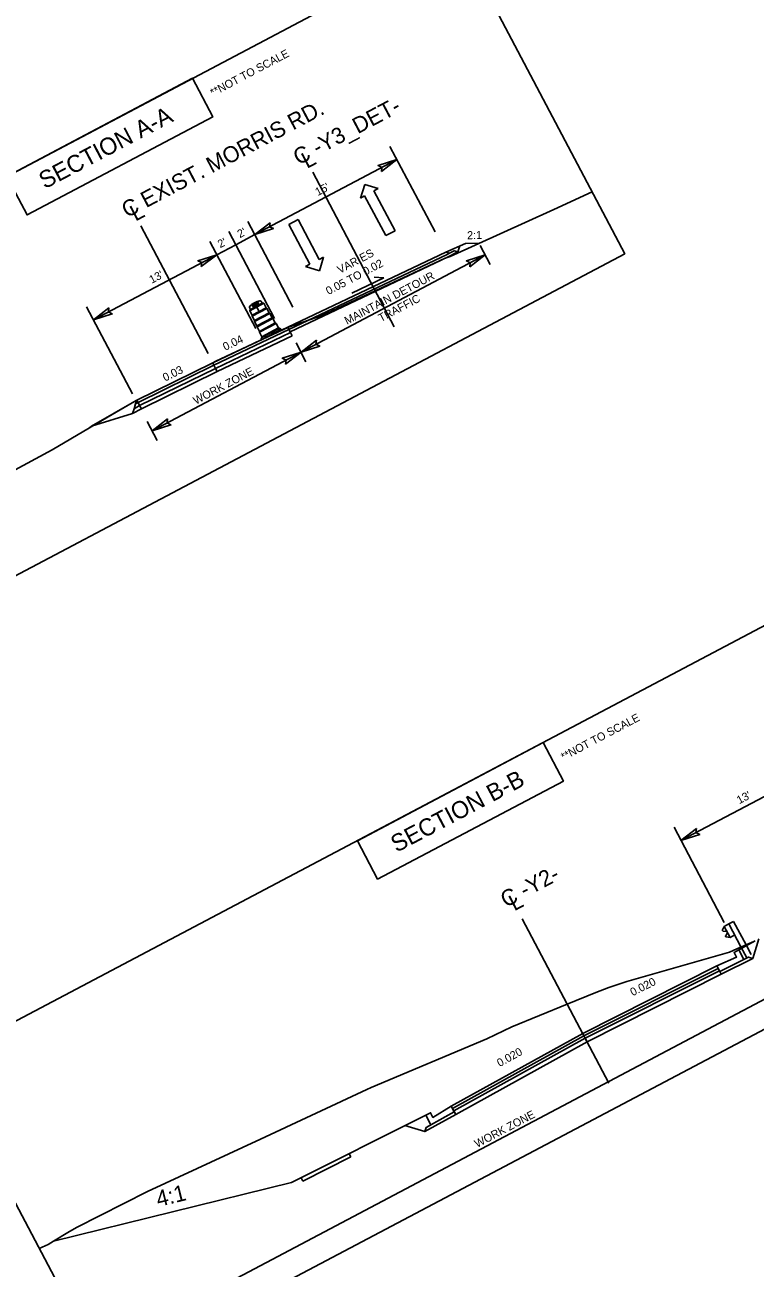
# Model space of a CAD drawing. Extents: x 1487176 to 1495274, y 497106 to 503692.
# Drawn here: x 1488684.4 to 1488752.5, y 497172.6 to 497288.5 of the extents above; entities that cross this region are included whole.
import ezdxf

# ---------------------------------------------------------------- set-up
doc = ezdxf.new("R2010")
doc.units = 0
for name, color, linetype in [('Default', 7, 'Continuous'), ('Exist XS Ground Line', 7, 'Continuous'), ('Prop Terminator CELL', 7, 'Continuous'), ('Typical Guardrail CELL', 7, 'Continuous'), ('Typical Hinge Slope Interstate CELL', 7, 'Continuous'), ('Typical Pavement Slope Information CELL', 7, 'Continuous'), ('WZ OSDR CELL', 7, 'Continuous')]:
    doc.layers.add(name, color=color, linetype=linetype)

msp = doc.modelspace()

# ---------------------------------------------------------------- linework, layer by layer
at = {"layer": 'Default'}
for p, q in [((1488722.67, 497269.16), (1488718.45, 497277.14)), ((1488719.1, 497275.91), (1488705.84, 497268.91)), ((1488718.85, 497260.33), (1488711.25, 497274.72)), ((1488716.1, 497273.6), (1488715.69, 497272.32)), ((1488717.36, 497273.2), (1488716.1, 497273.6)), ((1488716.96, 497272.99), (1488717.36, 497273.2)), ((1488718.92, 497269.28), (1488716.96, 497272.99)), ((1488715.69, 497272.32), (1488716.09, 497272.53)), ((1488716.09, 497272.53), (1488718.05, 497268.82)), ((1488701.51, 497257.82), (1488695.23, 497269.73)), ((1488709.4, 497262.16), (1488705.19, 497270.13)), ((1488709.01, 497269.86), (1488709.89, 497270.33)), ((1488710.97, 497266.15), (1488709.01, 497269.86)), ((1488709.89, 497270.33), (1488711.85, 497266.61)), ((1488718.05, 497268.82), (1488718.92, 497269.28)), ((1488705.93, 497260.16), (1488701.65, 497268.26)), ((1488707.7, 497261.09), (1488703.42, 497269.2)), ((1488704.07, 497267.97), (1488705.84, 497268.91)), ((1488702.3, 497267.04), (1488690.8, 497260.97)), ((1488702.3, 497267.04), (1488704.07, 497267.97)), ((1488727.33, 497267.02), (1488710.16, 497257.95)), ((1488727.8, 497266.14), (1488726.87, 497267.91)), ((1488710.58, 497265.94), (1488710.97, 497266.15)), ((1488711.87, 497265.55), (1488710.58, 497265.94)), ((1488711.85, 497266.61), (1488712.25, 497266.82)), ((1488712.25, 497266.82), (1488711.87, 497265.55)), ((1488694.44, 497254.09), (1488690.16, 497262.19)), ((1488709.15, 497259.86), (1488708.92, 497260.3)), ((1488710.62, 497257.07), (1488709.69, 497258.84)), ((1488710.16, 497257.95), (1488696.27, 497250.62)), ((1488696.74, 497249.74), (1488695.8, 497251.5)), ((1488757.08, 497218.52), (1488745.58, 497212.45)), ((1488749.62, 497204.81), (1488744.94, 497213.68)), ((1488766.66, 497204.67), (1488692.23, 497165.37)), ((1488730.77, 497205.16), (1488738.86, 497189.84)), ((1488714.79, 497182.96), (1488714.64, 497183.25)), ((1488710.32, 497180.71), (1488710.17, 497181.01))]:
    msp.add_line(p, q, dxfattribs=at)
for points in [[(1488657.96, 497261.26), (1488724.81, 497296.56), (1488740.34, 497267.13), (1488673.49, 497231.84)], [(1488682.73, 497274.34), (1488700.04, 497283.48), (1488701.93, 497279.89), (1488684.62, 497270.75)], [(1488676.52, 497191.9), (1488777.22, 497245.07), (1488792.75, 497215.65), (1488692.05, 497162.48)], [(1488715.41, 497212.43), (1488732.73, 497221.58), (1488734.62, 497217.99), (1488717.3, 497208.85)], [(1488736.54, 497194.24), (1488736.48, 497194.35), (1488736.48, 497194.35), (1488736.54, 497194.24)], [(1488736.54, 497194.24), (1488736.48, 497194.35), (1488736.48, 497194.35), (1488736.54, 497194.24)]]:
    msp.add_lwpolyline(points, close=True, dxfattribs=at)
for points in [[(1488723.65, 497267.29), (1488725.5, 497268.09)], [(1488725.5, 497268.09), (1488726.76, 497268.11)], [(1488708.92, 497260.3), (1488723.65, 497267.29)], [(1488708.92, 497260.3), (1488723.65, 497267.29)], [(1488708.92, 497260.3), (1488723.65, 497267.29)], [(1488723.77, 497267.07), (1488709.03, 497260.08)], [(1488709.03, 497260.08), (1488723.77, 497267.07)], [(1488723.65, 497267.29), (1488723.65, 497267.29)], [(1488723.65, 497267.29), (1488723.65, 497267.29)], [(1488723.65, 497267.29), (1488724, 497267.19)], [(1488723.77, 497267.07), (1488724, 497267.19), (1488724.44, 497267.41), (1488724.79, 497267.31)], [(1488724, 497267.19), (1488723.77, 497267.07)], [(1488724.79, 497267.31), (1488723.89, 497266.85)], [(1488723.89, 497266.85), (1488724.79, 497267.31)], [(1488724.79, 497267.31), (1488724.96, 497267.86)], [(1488709.15, 497259.86), (1488723.89, 497266.85)], [(1488723.89, 497266.85), (1488709.15, 497259.86)], [(1488701.92, 497256.97), (1488708.92, 497260.3)], [(1488701.92, 497256.97), (1488708.92, 497260.3)], [(1488709.03, 497260.08), (1488702.04, 497256.75)], [(1488702.04, 497256.75), (1488709.03, 497260.08)], [(1488708.92, 497260.3), (1488708.92, 497260.3)], [(1488709.03, 497260.08), (1488708.92, 497260.3)], [(1488708.92, 497260.3), (1488708.92, 497260.3)], [(1488708.92, 497260.3), (1488709.03, 497260.08)], [(1488709.19, 497259.79), (1488709.03, 497260.08)], [(1488709.03, 497260.08), (1488709.19, 497259.79)], [(1488709.19, 497259.79), (1488702.19, 497256.45)], [(1488702.19, 497256.45), (1488709.19, 497259.79)], [(1488702.35, 497256.16), (1488709.34, 497259.49)], [(1488709.34, 497259.49), (1488702.35, 497256.16)], [(1488709.34, 497259.49), (1488709.19, 497259.79)], [(1488709.19, 497259.79), (1488709.34, 497259.49)], [(1488701.92, 497256.97), (1488694.84, 497253.49)], [(1488701.92, 497256.97), (1488694.84, 497253.49)], [(1488694.96, 497253.27), (1488702.04, 497256.75)], [(1488702.04, 497256.75), (1488694.96, 497253.27)], [(1488702.04, 497256.75), (1488701.92, 497256.97)], [(1488702.04, 497256.75), (1488701.92, 497256.97)], [(1488702.19, 497256.45), (1488702.04, 497256.75)], [(1488702.19, 497256.45), (1488702.04, 497256.75)], [(1488695.11, 497252.98), (1488702.19, 497256.45)], [(1488702.19, 497256.45), (1488695.11, 497252.98)], [(1488702.35, 497256.16), (1488695.27, 497252.68)], [(1488695.27, 497252.68), (1488702.35, 497256.16)], [(1488702.35, 497256.16), (1488702.19, 497256.45)], [(1488702.35, 497256.16), (1488702.19, 497256.45)], [(1488694.84, 497253.49), (1488690.61, 497251.05)], [(1488694.96, 497253.27), (1488694.73, 497253.15), (1488694.59, 497252.69)], [(1488694.84, 497253.49), (1488694.73, 497253.15)], [(1488694.73, 497253.15), (1488694.96, 497253.27)], [(1488694.84, 497253.49), (1488694.84, 497253.49)], [(1488694.96, 497253.27), (1488694.84, 497253.49)], [(1488694.84, 497253.49), (1488694.84, 497253.49)], [(1488694.84, 497253.49), (1488694.96, 497253.27)], [(1488695.11, 497252.98), (1488694.96, 497253.27)], [(1488694.96, 497253.27), (1488695.11, 497252.98)], [(1488694.45, 497252.23), (1488690.61, 497251.05)], [(1488694.59, 497252.69), (1488694.45, 497252.23)], [(1488694.45, 497252.23), (1488695.27, 497252.68)], [(1488695.27, 497252.68), (1488694.45, 497252.23)], [(1488694.59, 497252.69), (1488695.11, 497252.98)], [(1488695.11, 497252.98), (1488694.59, 497252.69)], [(1488694.59, 497252.69), (1488694.59, 497252.69)], [(1488695.27, 497252.68), (1488695.11, 497252.98)], [(1488695.11, 497252.98), (1488695.27, 497252.68)], [(1488690.61, 497251.05), (1488690.45, 497250.91), (1488690.4, 497250.96)], [(1488749.34, 497199.98), (1488752.29, 497201.46), (1488752.85, 497203.27)], [(1488748.93, 497200.75), (1488750.76, 497201.58), (1488750.53, 497202.02), (1488750.97, 497202.26)], [(1488750.97, 497202.26), (1488751.44, 497201.36), (1488749.21, 497200.24)], [(1488750.76, 497201.58), (1488750.53, 497202.02), (1488750.97, 497202.26)], [(1488750.97, 497202.26), (1488752.5, 497203.1)], [(1488748.93, 497200.75), (1488750.76, 497201.58)], [(1488749.21, 497200.24), (1488751.89, 497201.58), (1488752.29, 497201.46)], [(1488752.29, 497201.46), (1488749.34, 497199.98)], [(1488736.42, 497194.46), (1488748.93, 497200.75)], [(1488736.42, 497194.46), (1488748.93, 497200.75)], [(1488736.54, 497194.24), (1488749.05, 497200.53)], [(1488749.05, 497200.53), (1488736.54, 497194.24)], [(1488749.17, 497200.31), (1488736.66, 497194.02)], [(1488736.66, 497194.02), (1488749.17, 497200.31)], [(1488749.34, 497199.98), (1488736.83, 497193.69)], [(1488736.83, 497193.69), (1488749.34, 497199.98)], [(1488749.21, 497200.24), (1488748.93, 497200.75)], [(1488748.93, 497200.75), (1488749.05, 497200.53)], [(1488749.05, 497200.53), (1488749.17, 497200.31)], [(1488749.17, 497200.31), (1488749.34, 497199.98)], [(1488749.34, 497199.98), (1488749.21, 497200.24)], [(1488736.42, 497194.46), (1488724.17, 497187.68)], [(1488736.42, 497194.46), (1488724.17, 497187.68)], [(1488736.54, 497194.24), (1488724.29, 497187.46)], [(1488724.29, 497187.46), (1488736.54, 497194.24)], [(1488724.41, 497187.24), (1488736.66, 497194.02)], [(1488736.66, 497194.02), (1488724.41, 497187.24)], [(1488736.54, 497194.24), (1488736.42, 497194.46)], [(1488736.54, 497194.24), (1488736.42, 497194.46)], [(1488736.66, 497194.02), (1488736.54, 497194.24)], [(1488736.66, 497194.02), (1488736.54, 497194.24)], [(1488736.83, 497193.69), (1488736.66, 497194.02)], [(1488736.83, 497193.69), (1488736.66, 497194.02)], [(1488724.58, 497186.9), (1488736.83, 497193.69)], [(1488736.83, 497193.69), (1488724.58, 497186.9)], [(1488724.45, 497187.16), (1488721.82, 497185.71), (1488721.7, 497185.31)], [(1488724.17, 497187.68), (1488722.46, 497186.64), (1488722.23, 497187.08), (1488721.78, 497186.85)], [(1488721.78, 497186.85), (1488722.26, 497185.95), (1488724.45, 497187.16)], [(1488722.46, 497186.64), (1488722.23, 497187.08), (1488721.78, 497186.85)], [(1488724.17, 497187.68), (1488722.46, 497186.64)], [(1488724.45, 497187.16), (1488724.17, 497187.68)], [(1488724.17, 497187.68), (1488724.29, 497187.46)], [(1488724.29, 497187.46), (1488724.41, 497187.24)], [(1488724.41, 497187.24), (1488724.58, 497186.9)], [(1488724.58, 497186.9), (1488724.45, 497187.16)], [(1488721.78, 497186.85), (1488709.27, 497180.56), (1488687.09, 497175.11)], [(1488724.58, 497186.9), (1488721.7, 497185.31), (1488719.85, 497185.87)], [(1488721.7, 497185.31), (1488724.58, 497186.9)], [(1488714.79, 497182.96), (1488710.32, 497180.71)]]:
    msp.add_lwpolyline(points, dxfattribs=at)
at = {"layer": 'Exist XS Ground Line'}
for points in [[(1488669.29, 497239.8), (1488674.04, 497241.95), (1488674.67, 497242.24), (1488675.03, 497242.43), (1488686.96, 497248.87), (1488692.19, 497251.92), (1488694.78, 497253.44), (1488701.92, 497256.97), (1488702.21, 497257.11), (1488708.98, 497260.28), (1488712.18, 497261.42), (1488720.16, 497265.1), (1488723.61, 497266.71), (1488724.06, 497266.89), (1488733.72, 497271.27), (1488737.3, 497272.89)], [(1488687.09, 497175.11), (1488688.41, 497175.9), (1488689.23, 497176.38), (1488695.85, 497179.73), (1488706.39, 497184.61), (1488716.29, 497189.25), (1488716.69, 497189.42), (1488727.49, 497193.97), (1488729.81, 497195.08), (1488734.98, 497197.2), (1488737.63, 497198.28), (1488738.86, 497198.75), (1488740.52, 497199.31), (1488750.1, 497202.05), (1488750.79, 497202.35), (1488752.36, 497203.04), (1488752.5, 497203.1)], [(1488685.75, 497174.42), (1488686.57, 497174.8), (1488687.09, 497175.11)]]:
    msp.add_lwpolyline(points, dxfattribs=at)
at = {"layer": 'Prop Terminator CELL'}
for points in [[(1488717.65, 497274.8), (1488719.1, 497275.91), (1488717.35, 497275.35), (1488717.7, 497275.17)], [(1488707.28, 497270.02), (1488705.84, 497268.91), (1488707.59, 497269.47), (1488707.23, 497269.65)], [(1488700.85, 497265.93), (1488702.3, 497267.04), (1488700.55, 497266.48), (1488700.9, 497266.3)], [(1488725.89, 497265.91), (1488727.33, 497267.02), (1488725.58, 497266.46), (1488725.94, 497266.28)], [(1488692.25, 497262.08), (1488690.8, 497260.97), (1488692.55, 497261.53), (1488692.2, 497261.71)], [(1488711.6, 497259.07), (1488710.16, 497257.95), (1488711.91, 497258.52), (1488711.55, 497258.69)], [(1488708.71, 497256.84), (1488710.16, 497257.95), (1488708.41, 497257.39), (1488708.76, 497257.22)], [(1488697.72, 497251.73), (1488696.27, 497250.62), (1488698.02, 497251.18), (1488697.67, 497251.36)], [(1488747.03, 497213.57), (1488745.58, 497212.45), (1488747.33, 497213.02), (1488746.98, 497213.19)]]:
    msp.add_lwpolyline(points, close=True, dxfattribs=at)
at = {"layer": 'Typical Guardrail CELL'}
for p, q in [((1488749.61, 497204.44), (1488749.45, 497204.12)), ((1488750.05, 497204.67), (1488749.61, 497204.44)), ((1488749.61, 497204.44), (1488750.16, 497203.41)), ((1488750.05, 497204.67), (1488750.49, 497204.9)), ((1488750.05, 497204.67), (1488751.21, 497202.47)), ((1488750.49, 497204.9), (1488751.65, 497202.71)), ((1488749.86, 497203.97), (1488749.51, 497204.01)), ((1488749.91, 497203.88), (1488749.75, 497203.57)), ((1488750.16, 497203.41), (1488749.81, 497203.46)), ((1488749.89, 497203.93), (1488749.86, 497203.97)), ((1488749.89, 497203.93), (1488749.91, 497203.88)), ((1488750.6, 497203.65), (1488750.16, 497203.41)), ((1488751.21, 497202.47), (1488751.65, 497202.71)), ((1488751.21, 497202.47), (1488751.69, 497201.58)), ((1488751.65, 497202.71), (1488752.13, 497201.81))]:
    msp.add_line(p, q, dxfattribs=at)
for centre, start, end in [((1488749.52, 497204.09), 152.8381, 262.8463), ((1488749.81, 497203.53), 152.841, 262.8717)]:
    msp.add_arc(centre, 0.0776, start, end, dxfattribs=at)
at = {"layer": 'Typical Pavement Slope Information CELL'}
for q in [(1488714.9, 497263.45), (1488716.98, 497264.95)]:
    msp.add_line((1488717.89, 497264.88), q, dxfattribs=at)
at = {"layer": 'WZ OSDR CELL'}
for p, q in [((1488705.38, 497261.82), (1488706.68, 497262.51)), ((1488705.44, 497261.94), (1488706.55, 497262.53)), ((1488706.18, 497262.55), (1488706.18, 497262.56)), ((1488706.55, 497262.53), (1488706.48, 497262.66)), ((1488706.68, 497262.51), (1488706.9, 497262.09)), ((1488705.44, 497261.94), (1488705.37, 497262.07)), ((1488705.38, 497261.82), (1488705.6, 497261.41)), ((1488705.6, 497261.41), (1488706.9, 497262.09)), ((1488705.6, 497261.41), (1488705.61, 497261.32)), ((1488705.61, 497261.32), (1488706.97, 497262.04)), ((1488705.61, 497261.32), (1488705.83, 497260.9)), ((1488705.63, 497262.26), (1488705.62, 497262.26)), ((1488705.83, 497260.9), (1488707.19, 497261.62)), ((1488705.83, 497260.82), (1488707.25, 497261.57)), ((1488706.05, 497260.4), (1488707.47, 497261.15)), ((1488706.9, 497262.09), (1488706.97, 497262.04)), ((1488706.97, 497262.04), (1488707.19, 497261.62)), ((1488707.19, 497261.62), (1488707.25, 497261.57)), ((1488707.25, 497261.57), (1488707.47, 497261.15)), ((1488707.47, 497261.15), (1488707.54, 497261.1)), ((1488705.83, 497260.9), (1488705.83, 497260.82)), ((1488705.83, 497260.82), (1488706.05, 497260.4)), ((1488706.05, 497260.4), (1488706.06, 497260.32)), ((1488706.06, 497260.32), (1488707.54, 497261.1)), ((1488706.06, 497260.32), (1488706.28, 497259.9)), ((1488706.28, 497259.9), (1488707.76, 497260.69)), ((1488706.28, 497259.82), (1488707.83, 497260.63)), ((1488706.5, 497259.4), (1488708.05, 497260.22)), ((1488706.5, 497259.31), (1488708.13, 497260.17)), ((1488706.5, 497259.13), (1488708.27, 497260.07)), ((1488707.54, 497261.1), (1488707.76, 497260.69)), ((1488707.76, 497260.69), (1488707.83, 497260.63)), ((1488707.83, 497260.63), (1488708.05, 497260.22)), ((1488708.05, 497260.22), (1488708.12, 497260.16)), ((1488708.27, 497260.07), (1488708.23, 497260.14)), ((1488706.28, 497259.9), (1488706.28, 497259.82)), ((1488706.28, 497259.82), (1488706.5, 497259.4)), ((1488706.5, 497259.13), (1488706.46, 497259.2)), ((1488706.5, 497259.4), (1488706.51, 497259.31))]:
    msp.add_line(p, q, dxfattribs=at)
for points in [[(1488705.61, 497261.32), (1488706.29, 497261.68), (1488705.92, 497262.37), (1488705.89, 497262.35), (1488705.86, 497262.34), (1488705.84, 497262.32), (1488705.81, 497262.31), (1488705.78, 497262.29), (1488705.75, 497262.27), (1488705.72, 497262.25), (1488705.7, 497262.23), (1488705.69, 497262.23), (1488705.67, 497262.23), (1488705.66, 497262.23), (1488705.65, 497262.24), (1488705.64, 497262.24), (1488705.63, 497262.25), (1488705.62, 497262.27), (1488705.62, 497262.28), (1488705.62, 497262.3), (1488705.62, 497262.31), (1488705.63, 497262.32), (1488705.64, 497262.33), (1488705.66, 497262.35), (1488705.69, 497262.37), (1488705.76, 497262.42), (1488705.81, 497262.44), (1488705.85, 497262.46), (1488705.87, 497262.48), (1488705.82, 497262.56), (1488705.78, 497262.54), (1488705.74, 497262.52), (1488705.69, 497262.49), (1488705.65, 497262.46), (1488705.6, 497262.43), (1488705.55, 497262.39), (1488705.5, 497262.35), (1488705.47, 497262.32), (1488705.42, 497262.27), (1488705.4, 497262.25), (1488705.39, 497262.24), (1488705.38, 497262.22), (1488705.37, 497262.2), (1488705.36, 497262.18), (1488705.35, 497262.15), (1488705.35, 497262.13), (1488705.36, 497262.11), (1488705.36, 497262.09), (1488705.37, 497262.07), (1488705.44, 497261.94), (1488705.43, 497261.93), (1488705.42, 497261.92), (1488705.41, 497261.9), (1488705.4, 497261.87), (1488705.39, 497261.85), (1488705.38, 497261.82), (1488705.6, 497261.41)], [(1488706.97, 497262.04), (1488706.29, 497261.68), (1488705.92, 497262.37), (1488705.98, 497262.4), (1488706.02, 497262.42), (1488706.06, 497262.44), (1488706.09, 497262.45), (1488706.12, 497262.46), (1488706.15, 497262.47), (1488706.16, 497262.48), (1488706.17, 497262.49), (1488706.18, 497262.5), (1488706.19, 497262.52), (1488706.19, 497262.53), (1488706.19, 497262.54), (1488706.18, 497262.56), (1488706.17, 497262.57), (1488706.15, 497262.58), (1488706.14, 497262.58), (1488706.13, 497262.58), (1488706.12, 497262.58), (1488706.11, 497262.58), (1488706.09, 497262.57), (1488706.06, 497262.56), (1488706.04, 497262.55), (1488706.01, 497262.54), (1488705.98, 497262.53), (1488705.94, 497262.51), (1488705.92, 497262.5), (1488705.89, 497262.49), (1488705.87, 497262.48), (1488705.82, 497262.56), (1488705.86, 497262.58), (1488705.89, 497262.6), (1488705.94, 497262.62), (1488705.97, 497262.63), (1488706.01, 497262.65), (1488706.05, 497262.66), (1488706.1, 497262.68), (1488706.14, 497262.69), (1488706.2, 497262.71), (1488706.25, 497262.72), (1488706.29, 497262.73), (1488706.31, 497262.74), (1488706.33, 497262.74), (1488706.35, 497262.74), (1488706.37, 497262.74), (1488706.39, 497262.73), (1488706.41, 497262.72), (1488706.43, 497262.71), (1488706.44, 497262.7), (1488706.46, 497262.69), (1488706.47, 497262.67), (1488706.48, 497262.66), (1488706.48, 497262.66), (1488706.55, 497262.53), (1488706.58, 497262.53), (1488706.6, 497262.53), (1488706.62, 497262.52), (1488706.64, 497262.52), (1488706.66, 497262.51), (1488706.67, 497262.51), (1488706.68, 497262.51), (1488706.9, 497262.09)], [(1488705.83, 497260.9), (1488707.19, 497261.62), (1488707.25, 497261.57), (1488707.47, 497261.15), (1488707.54, 497261.1), (1488706.06, 497260.32), (1488706.05, 497260.4), (1488705.83, 497260.82)], [(1488706.28, 497259.9), (1488707.76, 497260.69), (1488707.83, 497260.63), (1488708.05, 497260.22), (1488708.12, 497260.16), (1488708.13, 497260.17), (1488708.15, 497260.18), (1488708.16, 497260.18), (1488708.18, 497260.18), (1488708.19, 497260.17), (1488708.2, 497260.17), (1488708.21, 497260.16), (1488708.22, 497260.15), (1488708.23, 497260.14), (1488708.23, 497260.14), (1488708.27, 497260.07), (1488706.5, 497259.13), (1488706.46, 497259.2), (1488706.46, 497259.21), (1488706.46, 497259.23), (1488706.46, 497259.24), (1488706.46, 497259.25), (1488706.46, 497259.26), (1488706.46, 497259.27), (1488706.47, 497259.29), (1488706.48, 497259.3), (1488706.49, 497259.3), (1488706.5, 497259.31), (1488706.51, 497259.31), (1488706.5, 497259.4), (1488706.28, 497259.82)]]:
    msp.add_lwpolyline(points, close=True, dxfattribs=at)
for centre, radius, start, end in [((1488706.65, 497261), 1.77, 100.8859, 134.7843), ((1488705.67, 497262.29), 0.0548, 126.5091, 207.8351), ((1488706.69, 497260.91), 1.77, 109.1611, 126.5091), ((1488706.75, 497260.81), 1.77, 109.6863, 125.9838), ((1488706.13, 497262.53), 0.0548, 27.8351, 109.1611), ((1488706.13, 497262.52), 0.0548, 289.6863, 27.8351), ((1488706.34, 497262.58), 0.157, 27.8351, 100.8859), ((1488706.57, 497262.26), 0.271, 67.3216, 95.5291), ((1488705.51, 497262.14), 0.157, 134.7843, 207.8351), ((1488705.65, 497261.77), 0.271, 140.1411, 168.3486), ((1488705.68, 497262.28), 0.0548, 207.8351, 305.9838), ((1488708.16, 497260.1), 0.0783, 27.8351, 117.8351), ((1488706.53, 497259.24), 0.0783, 117.8351, 207.8351)]:
    msp.add_arc(centre, radius, start, end, dxfattribs=at)

# ---------------------------------------------------------------- texts
at = {"layer": 'Default'}
for s, height, rotation, p in [('**NOT TO SCALE', 0.75, 27.8351, (1488701.93, 497281.76)), ('SECTION A-A', 1.6, 27.8351, (1488686.26, 497273.13)), ("15'", 0.75, 27.8351, (1488711.72, 497272.5)), ("2'", 0.75, 27.8351, (1488704.46, 497268.58)), ('2:1', 0.75, 1.27, (1488725.65, 497268.48)), ("2'", 0.75, 27.8351, (1488702.63, 497267.64)), ('VARIES ', 0.75, 27.8351, (1488713.78, 497265.25)), ('0.05 TO 0.02', 0.75, 27.8351, (1488712.72, 497263.27)), ("13'", 0.75, 27.8351, (1488696.24, 497264.33)), ('MAINTAIN DETOUR', 0.75, 27.8351, (1488714.45, 497260.5)), ('TRAFFIC', 0.75, 27.8351, (1488717.61, 497260.75)), ('0.04', 0.75, 25.4758, (1488703.09, 497258.08)), ('0.03', 0.75, 26.1396, (1488697.49, 497255.21)), ('WORK ZONE', 0.75, 27.8351, (1488700.35, 497253.05)), ('**NOT TO SCALE', 0.75, 27.8351, (1488734.62, 497219.86)), ('SECTION B-B', 1.6, 27.8351, (1488719.06, 497211.29)), ("13'", 0.75, 27.8351, (1488751.02, 497215.82)), ('0.020', 0.75, 26.6893, (1488741.08, 497197.92)), ('0.020', 0.75, 28.9809, (1488728.68, 497191.32)), ('WORK ZONE', 0.75, 27.8351, (1488726.58, 497183.79)), ('4:1', 1.5, 13.7988, (1488696.85, 497178.28))]:
    msp.add_text(s, height=height, rotation=rotation, dxfattribs=at).set_placement(p)
at = {"layer": 'Typical Hinge Slope Interstate CELL'}
for s, p in [('C EXIST. MORRIS RD.', (1488693.94, 497270.44)), ('C -Y3_DET- ', (1488709.93, 497275.35)), ('L', (1488710.71, 497275.03)), ('L', (1488694.72, 497270.12)), ('C -Y2- ', (1488729.26, 497206.16)), ('L', (1488730.04, 497205.84))]:
    msp.add_text(s, height=1.5, rotation=27.8351, dxfattribs=at).set_placement(p)

doc.saveas('drawing.dxf')
